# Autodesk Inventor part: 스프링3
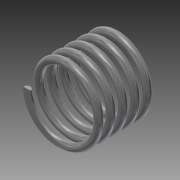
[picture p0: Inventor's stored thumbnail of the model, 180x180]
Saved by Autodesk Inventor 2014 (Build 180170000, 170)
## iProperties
Created: 2016-10
Part Number: 스프링3
Material: 강철, 탄소
Document SubType Name: Modeling
Designer: 703-16
Density: 7.87 g/cm^3
Appearance: 반연마
Mass: 6.8717 g
Surface Area: 17.7337 cm^2
Volume: 0.873151 cm^3
Author: 703-16
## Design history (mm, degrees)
sketch "스케치1"
  geometry: L1 (0, 0)-(-9, 0); L2 (-9, 0)-(-9, 16.67); L3 (-9, 16.67)-(0, 16.67); L4 (0, 16.67)-(0, 0); C1 r 1 at (-9, 0)
  constraints: 8 end point, 2 parallel, 1 centre point, 1 coincident, 1 horizontal, 1 perpendicular
  dimensions: "d0" = 16.66987 distance of L3.end L1.start (derived); "d1" = 2 diameter of C1; "d2" = 18 diameter of L2 L4
feature "코일1" sketch "스케치1" pitch "d3" = 10; turns "d5" = 5; dims "d4" = 16.66987 (= d0), "d6" = 0, angle "d7" = 90 deg, angle "d8" = 90 deg, "d9" = 0, "d10" = 0
node "작업 평면1"
sketch "스케치2"
  geometry: L1 (0, 0)-(-2, 0) reference; 1 further point
  constraints: 1 horizontal alignment
extrude "돌출1" cut sketch "스케치2" distance "d11" = 10; taper "d12" = 0 deg
sketch "스케치3"
  geometry: L1 (8, 0)-(10, 0) reference; 1 further point
  constraints: 1 horizontal alignment
extrude "돌출2" cut sketch "스케치3" distance "d13" = 10; taper "d14" = 0 deg
node "솔리드1"
node "절단 모서리 투영1"
node "절단 모서리 투영2"
